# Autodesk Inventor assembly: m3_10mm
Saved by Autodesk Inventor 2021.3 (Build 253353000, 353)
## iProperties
Created: 2022-05
Part Number: m3_10mm
Document SubType Name: Assembly
Designer: Administrator
Title: m3_10mm v1
Author: Administrator
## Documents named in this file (2)
- c:\worker\convert-fusion-r03\tmp\job-1\185\output\files\0fa6b6d8-5ae5-4a2f-92c7-634827d88ab4\m3_10mm v1.iam
- c:\worker\convert-fusion-r03\tmp\job-1\185\output\files\0fa6b6d8-5ae5-4a2f-92c7-634827d88ab4\90116A155_316 Stainless Steel Pan Head Phillips Screws.ipt
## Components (1 placed, 1 different names)
1. 90116A155_316 Stainless Steel Pan Head Phillips Screws:1
